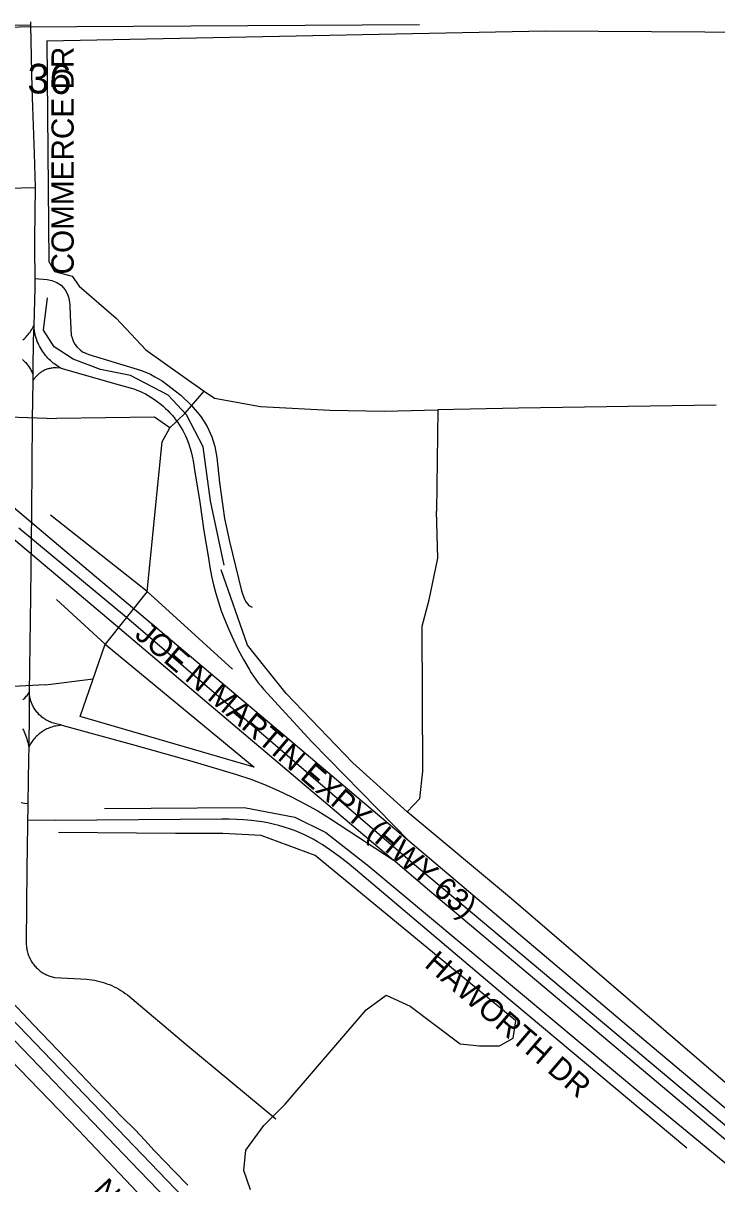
# Model space of a CAD drawing. Extents: x 1670563 to 1761545, y 515755 to 578944.
# Drawn here: x 1720123 to 1722466, y 535106 to 539024 of the extents above; entities that cross this region are included whole.
import ezdxf

# ---------------------------------------------------------------- set-up
doc = ezdxf.new("R2010")
doc.units = 0
for name, color, linetype in [('5_sectionlines', 7, 'Continuous'), ('62_text', 7, 'Continuous'), ('RR Tracks', 7, 'Continuous'), ('SHP_LINE', 7, 'Continuous'), ('STREETCL', 7, 'Continuous'), ('STRNAMES', 7, 'Continuous')]:
    doc.layers.add(name, color=color, linetype=linetype)

# ---------------------------------------------------------------- blocks, each defined once
blk = doc.blocks.new('RR TRACKS02')
at = {"layer": 'RR Tracks'}
for p, q in [((1720066.6, 535738.8), (1720158.1, 535642.9)), ((1720158.1, 535642.9), (1720268.9, 535527.6)), ((1720268.9, 535527.6), (1720363.3, 535429)), ((1720363.3, 535429), (1720404.7, 535386)), ((1720404.7, 535386), (1720455, 535333.2)), ((1720455, 535333.2), (1720500.9, 535287.8)), ((1720500.9, 535287.8), (1720534.1, 535252.7)), ((1720534.1, 535252.7), (1720566.1, 535218.7)), ((1720566.1, 535218.7), (1720605, 535177.4)), ((1720605, 535177.4), (1720631.5, 535150.1)), ((1720631.5, 535150.1), (1720678.7, 535101))]:
    blk.add_line(p, q, dxfattribs=at)

msp = doc.modelspace()

# ---------------------------------------------------------------- linework, layer by layer
at = {"layer": '5_sectionlines'}
msp.add_lwpolyline([(1717513.9, 538978.6), (1720109.2, 539011.6), (1721461.9, 539019.1)], dxfattribs=at)
at = {"layer": 'SHP_LINE'}
for points in [[(1720203, 538964), (1721887, 538998), (1722783, 538992), (1723831, 538992), (1723868, 538974), (1723856, 537753)], [(1720203, 538964), (1720210, 538219), (1720229, 538185), (1720289, 538170), (1720312, 538136), (1720437, 538028), (1720537, 537921), (1720662, 537832), (1720734, 537782)], [(1716945, 538927), (1717499, 538359), (1718014, 537823), (1718693, 537111), (1720080, 535667), (1721972, 533700)], [(1720675, 537702), (1720613, 537768), (1720486, 537834), (1720384, 537855), (1720292, 537890), (1720228, 537931), (1720192, 537987), (1720205, 538097)], [(1719435, 538027), (1720006, 537568), (1720055, 537550), (1720058, 537652), (1720074, 537695), (1720236, 537689)], [(1720670, 537707), (1720734, 537782)], [(1720734, 537782), (1720769, 537758), (1720925, 537730), (1721159, 537717), (1721343, 537714), (1721524, 537719)], [(1722464, 537734), (1721796, 537724), (1721524, 537719)], [(1720618, 537658), (1720567, 537694), (1720236, 537689)], [(1720618, 537658), (1720670, 537707)], [(1720802, 537194), (1720756, 537411), (1720731, 537594), (1720675, 537702)], [(1721524, 537719), (1721519, 537376)], [(1720542, 537105), (1720593, 537610), (1720618, 537658)], [(1720542, 537105), (1720215, 537363)], [(1721420, 536361), (1721463, 536407), (1721473, 536499), (1721471, 536988), (1721494, 537077), (1721524, 537218), (1721519, 537376)], [(1720472, 537018), (1720108, 537319)], [(1721420, 536361), (1721236, 536527), (1721011, 536761), (1720881, 536924), (1720792, 537179)], [(1720400, 536928), (1720236, 537078)], [(1720542, 537105), (1720400, 536928)], [(1720830, 536843), (1720542, 537105)], [(1722723, 535111), (1721430, 536195), (1720472, 537018)], [(1720316, 536683), (1720400, 536928)], [(1720400, 536928), (1720903, 536512)], [(1720198, 536790), (1720359, 536810)], [(1720198, 536790), (1720088, 536785)], [(1720903, 536512), (1720316, 536683)], [(1720398, 536373), (1720869, 536376), (1721041, 536343), (1721145, 536292), (1721291, 536178), (1722213, 535409), (1722571, 535114)], [(1722791, 535192), (1721772, 536068), (1721420, 536361)], [(1720891, 535086), (1720868, 535151), (1720875, 535219), (1720936, 535303), (1721008, 535375), (1721281, 535693), (1721349, 535743), (1721430, 535705), (1721599, 535578), (1721664, 535572), (1721732, 535572), (1721778, 535598), (1721787, 535656), (1721109, 536214), (1720927, 536282), (1720797, 536288), (1720638, 536288), (1720242, 536292)], [(1721755, 533769), (1721429, 534123), (1720982, 534585), (1720746, 534827), (1720310, 535287), (1719979, 535628)]]:
    msp.add_lwpolyline(points, dxfattribs=at)
at = {"layer": 'STREETCL'}
for points in [[(1720148.4, 539028), (1720148.2, 539016.9)], [(1720148.2, 539016.9), (1719670.9, 539012.9), (1719127.6, 539007.3)], [(1720148.2, 539016.9), (1720152.9, 538804.9), (1720160.8, 538584.1), (1720163.3, 538468.9)], [(1717072.9, 538715.7), (1717264.4, 538514.7), (1717510.3, 538264.3), (1717644.4, 538130.2), (1717873.6, 537900.7), (1718183.4, 537583.4), (1718347.1, 537415.1), (1718556.6, 537194.6), (1718908.4, 536828.7), (1719250.4, 536472.2), (1719637.9, 536070.3), (1720069.6, 535615.9), (1720515, 535151.1), (1721005.6, 534643.8), (1721526.6, 534096.2), (1721830.2, 533779.6)], [(1719874.9, 538462.2), (1720163.3, 538468.9)], [(1720163.3, 538468.9), (1720163, 538382.3), (1720160.9, 538295.8), (1720162.5, 538130.2), (1720158.6, 538002.8)], [(1718950.4, 538352.1), (1719123.4, 538207), (1719173, 538165), (1719214.3, 538129.6), (1719589.5, 537811.7), (1720242.3, 537262), (1721005.8, 536619.3), (1721524.5, 536180.2), (1722198.3, 535611.1), (1722953.7, 534976), (1723788.9, 534274.5), (1724544.5, 533631.9), (1724982.8, 533261.7), (1725686.8, 532669.5), (1726432.6, 532038.6), (1727302.6, 531305.4), (1727848.2, 530843.4), (1728084.3, 530646.1), (1728237.3, 530523.1), (1728394.2, 530405.1)], [(1718979.7, 538220.5), (1719085.6, 538130.6), (1719464.7, 537808.7), (1719917.2, 537427.8), (1720391.1, 537029.5), (1720831.3, 536657.3), (1721210.7, 536336.3), (1721372.6, 536199.1)], [(1720162.2, 538162), (1720204.5, 538158.4), (1720219.7, 538155.5), (1720236.3, 538148.1), (1720251.1, 538138.9), (1720264.4, 538124.1), (1720273.3, 538109), (1720277.7, 538095.3), (1720279.9, 538081.3), (1720281, 538072.4), (1720282.1, 538037), (1720285.1, 537971), (1720288.1, 537961.4), (1720292.2, 537950.3), (1720298.1, 537940.7), (1720305.5, 537930), (1720315.1, 537920.8), (1720323.9, 537914.5), (1720337.2, 537908.2), (1720345.4, 537905.3), (1720523.2, 537851.5), (1720552.8, 537838.9), (1720567.9, 537830.1), (1720593.1, 537816.4), (1720607.5, 537805.3), (1720655.4, 537768.2), (1720691.2, 537733.2), (1720723.7, 537695.9), (1720744.8, 537662.6), (1720760.7, 537627.6), (1720770, 537594.8), (1720777.4, 537557.9), (1720786.3, 537473), (1720803, 537351.2), (1720820.3, 537273.7), (1720860.2, 537107.9), (1720869.1, 537082.1), (1720875.8, 537068.9), (1720885.4, 537057.8), (1720896.9, 537051.9)], [(1720122.5, 537954.8), (1720126.3, 537958.2), (1720129.9, 537961.7), (1720133.5, 537965.3), (1720136.9, 537969), (1720140.2, 537972.9), (1720143.3, 537976.9), (1720146.3, 537981), (1720149.2, 537985.1), (1720151.9, 537989.4), (1720154.5, 537993.8), (1720156.9, 537998.3), (1720158.6, 538002.4)], [(1720158.6, 538002.8), (1720157.2, 537953.6), (1720155.8, 537853.7)], [(1720249.9, 537859.5), (1720244.6, 537862.6), (1720239.5, 537865.8), (1720234.4, 537869.3), (1720229.5, 537872.9), (1720224.7, 537876.6), (1720220, 537880.5), (1720215.4, 537884.6), (1720211, 537888.8), (1720206.8, 537893.2), (1720202.7, 537897.7), (1720198.7, 537902.4), (1720194.9, 537907.2), (1720191.3, 537912.1), (1720187.9, 537917.1), (1720184.6, 537922.3), (1720181.5, 537927.5), (1720178.6, 537932.9), (1720175.8, 537938.3), (1720173.3, 537943.9), (1720170.9, 537949.5), (1720168.8, 537955.2), (1720166.8, 537961), (1720165, 537966.8), (1720163.4, 537972.7), (1720162.1, 537978.7), (1720160.9, 537984.7), (1720159.9, 537990.7), (1720159.2, 537996.7), (1720158.6, 538002.8)], [(1720120.7, 537888.3), (1720123.6, 537885.8), (1720126.4, 537883.2), (1720129.2, 537880.5), (1720131.9, 537877.8), (1720134.5, 537874.9), (1720136.9, 537872), (1720139.3, 537869), (1720141.6, 537865.9), (1720143.7, 537862.7), (1720145.8, 537859.4), (1720147.7, 537856.1), (1720149.5, 537852.7), (1720151.2, 537849.3), (1720152.8, 537845.8), (1720154.3, 537842.2), (1720155.6, 537838.6)], [(1720249.9, 537859.5), (1720236, 537860.2), (1720233, 537860.3), (1720230, 537860.3), (1720226.9, 537860.1), (1720223.9, 537859.9), (1720220.9, 537859.6), (1720217.9, 537859.1), (1720214.9, 537858.6), (1720211.9, 537858), (1720209, 537857.2), (1720206.1, 537856.4), (1720203.2, 537855.4), (1720200.3, 537854.4), (1720197.5, 537853.3), (1720194.7, 537852), (1720192, 537850.7), (1720189.3, 537849.3), (1720186.7, 537847.8), (1720184.1, 537846.1), (1720181.6, 537844.5), (1720179.2, 537842.7), (1720176.8, 537840.8), (1720174.4, 537838.9), (1720172.2, 537836.8), (1720170, 537834.7), (1720167.9, 537832.6), (1720165.8, 537830.3), (1720163.9, 537828), (1720162, 537825.6), (1720160.2, 537823.2), (1720158.5, 537820.7), (1720156.9, 537818.1), (1720155.3, 537815.5)], [(1720155.8, 537853.7), (1720155.3, 537815.5)], [(1720249.9, 537859.5), (1720451.6, 537802.3), (1720497.3, 537788.9), (1720507.1, 537785.2), (1720516.8, 537781.1), (1720526.4, 537776.7), (1720535.8, 537772), (1720545, 537766.9), (1720554.1, 537761.6), (1720562.9, 537755.9), (1720571.6, 537750), (1720580.1, 537743.7), (1720588.3, 537737.2), (1720596.3, 537730.4), (1720604.1, 537723.3), (1720611.7, 537716), (1720619, 537708.4), (1720626, 537700.6), (1720632.7, 537692.5), (1720639.2, 537684.2), (1720645.4, 537675.7), (1720651.3, 537667), (1720656.9, 537658.1), (1720662.2, 537649), (1720667.2, 537639.8), (1720671.8, 537630.3), (1720676.2, 537620.7), (1720681.4, 537606.2), (1720686.1, 537591.6), (1720690.3, 537576.8), (1720694, 537561.8), (1720697.3, 537546.8), (1720700, 537531.6), (1720702.3, 537516.4), (1720719.8, 537406.8), (1720733.6, 537310.1), (1720749.2, 537217.6), (1720753.8, 537187.5), (1720759.4, 537157.6), (1720766.1, 537127.9), (1720773.7, 537098.4), (1720782.4, 537069.2), (1720792.1, 537040.3), (1720802.8, 537011.8), (1720817.3, 536977), (1720833, 536942.7), (1720849.7, 536908.9), (1720867.4, 536875.7), (1720886.2, 536843), (1720893.4, 536831.3), (1720900.9, 536819.7), (1720908.7, 536808.4), (1720917, 536797.4), (1720925.5, 536786.6), (1720934.4, 536776.1), (1721097.6, 536598), (1721429.5, 536260.6)], [(1720155.3, 537815.5), (1720153.6, 537686.9), (1720151, 537372.1), (1720147.4, 537088.2), (1720143.8, 536763.9)], [(1720122.3, 536740.6), (1720125.3, 536743.2), (1720128.3, 536745.8), (1720131.1, 536748.6), (1720133.8, 536751.5), (1720136.5, 536754.5), (1720139, 536757.5), (1720141.5, 536760.7), (1720143.8, 536763.9)], [(1720143.8, 536763.9), (1720143, 536696.7), (1720141.7, 536578.7)], [(1720253.9, 536653.7), (1720225.1, 536661.1), (1720221.3, 536662.3), (1720217.5, 536663.6), (1720213.8, 536665.1), (1720210.2, 536666.8), (1720206.6, 536668.5), (1720203.1, 536670.4), (1720199.6, 536672.4), (1720196.3, 536674.5), (1720193, 536676.7), (1720189.7, 536679), (1720186.6, 536681.5), (1720183.5, 536684), (1720180.6, 536686.7), (1720177.7, 536689.4), (1720174.9, 536692.3), (1720172.2, 536695.2), (1720169.6, 536698.3), (1720167.2, 536701.4), (1720164.8, 536704.6), (1720162.6, 536707.9), (1720160.4, 536711.2), (1720158.4, 536714.7), (1720156.5, 536718.2), (1720154.8, 536721.7), (1720153.1, 536725.4), (1720151.6, 536729), (1720150.2, 536732.8), (1720148.9, 536736.6), (1720147.8, 536740.4), (1720146.8, 536744.2), (1720145.9, 536748.1), (1720145.2, 536752), (1720144.6, 536756), (1720144.1, 536759.9), (1720143.8, 536763.9)], [(1720121.4, 536642.1), (1720124.2, 536636.7), (1720126.9, 536631.2), (1720129.3, 536625.6), (1720131.5, 536620), (1720133.6, 536614.3), (1720135.4, 536608.5), (1720137.1, 536602.6), (1720138.6, 536596.7), (1720139.8, 536590.7), (1720140.8, 536584.7), (1720141.7, 536578.7)], [(1720253.9, 536653.7), (1720233.2, 536651.2), (1720228.8, 536650.2), (1720224.4, 536649.1), (1720220.1, 536647.8), (1720215.9, 536646.4), (1720211.7, 536644.8), (1720207.6, 536643.1), (1720203.5, 536641.2), (1720199.5, 536639.2), (1720195.5, 536637.1), (1720191.7, 536634.8), (1720187.9, 536632.4), (1720184.2, 536629.9), (1720180.6, 536627.2), (1720177.1, 536624.4), (1720173.6, 536621.5), (1720170.3, 536618.5), (1720167.1, 536615.4), (1720164, 536612.1), (1720161, 536608.8), (1720158.2, 536605.3), (1720155.4, 536601.8), (1720152.8, 536598.1), (1720150.3, 536594.4), (1720148, 536590.6), (1720145.7, 536586.7), (1720143.6, 536582.7), (1720141.7, 536578.7)], [(1720253.9, 536653.7), (1720492.3, 536589), (1720700.6, 536530.4), (1720844.1, 536488), (1720891.5, 536471.5), (1720938.3, 536453.3), (1720984.4, 536433.5), (1721029.8, 536412.1), (1721074.4, 536389.1), (1721118.2, 536364.5), (1721161.1, 536338.4), (1721372.6, 536199.1)], [(1720141.7, 536578.7), (1720141.3, 536542.7), (1720139.1, 536389.7)], [(1720116.2, 536393), (1720127.6, 536391.2), (1720139.1, 536389.7)], [(1720139.1, 536389.7), (1720136, 536169.4), (1720133.4, 535920.5)], [(1722364.5, 535226.1), (1721728.6, 535758.3), (1721245.4, 536167), (1721218.2, 536189.3), (1721190.2, 536210.7), (1721161.7, 536231.3), (1721132.4, 536250.9), (1721117.6, 536260.1), (1721102.5, 536268.8), (1721087, 536277), (1721071.3, 536284.7), (1721055.3, 536291.7), (1721039.1, 536298.2), (1721022.6, 536304.2), (1721004.6, 536310), (1720986.3, 536315.2), (1720967.9, 536319.9), (1720949.4, 536323.9), (1720930.8, 536327.3), (1720912, 536330.2), (1720893.2, 536332.4), (1720868.5, 536334.5), (1720843.8, 536335.9), (1720819.1, 536336.5), (1720794.3, 536336.3), (1720231.4, 536332.5), (1720138.3, 536333.8)], [(1728653.2, 530115.7), (1728352.7, 530332.4), (1728275.7, 530388.1), (1728200.3, 530445.9), (1728126.6, 530505.9), (1727694.6, 530868), (1727158, 531319.4), (1726440.9, 531926.6), (1726228.5, 532103.9), (1725809, 532459.7), (1725505.4, 532713.2), (1725193.8, 532977.5), (1725010.1, 533132.4), (1724856.7, 533260.6), (1724520.2, 533546.7), (1723891, 534077.5), (1723306.1, 534568.7), (1722651.6, 535122.4), (1722033.9, 535643), (1721503.5, 536088.2), (1721372.6, 536199.1)], [(1720133.4, 535920.5), (1720133.4, 535916.3), (1720133.6, 535912.2), (1720133.9, 535908.1), (1720134.4, 535904), (1720135, 535899.9), (1720135.7, 535895.9), (1720136.6, 535891.9), (1720137.6, 535887.9), (1720138.8, 535883.9), (1720140.1, 535880), (1720141.5, 535876.1), (1720143.1, 535872.3), (1720144.8, 535868.6), (1720146.6, 535864.9), (1720148.5, 535861.2), (1720150.6, 535857.7), (1720152.8, 535854.2), (1720155.1, 535850.8), (1720157.6, 535847.4), (1720160.1, 535844.2), (1720162.8, 535841), (1720165.5, 535838), (1720168.4, 535835), (1720171.4, 535832.2), (1720174.4, 535829.4), (1720177.6, 535826.8), (1720180.8, 535824.2), (1720184.2, 535821.8), (1720187.6, 535819.5), (1720191.1, 535817.3), (1720194.7, 535815.2), (1720198.3, 535813.3), (1720202, 535811.5), (1720205.8, 535809.8), (1720209.6, 535808.3), (1720213.4, 535806.8), (1720217.4, 535805.6), (1720221.3, 535804.4), (1720225.3, 535803.4), (1720229.4, 535802.5), (1720337.6, 535796.4), (1720346.4, 535795.6), (1720355.1, 535794.4), (1720363.7, 535793), (1720372.3, 535791.3), (1720380.9, 535789.2), (1720389.4, 535786.9), (1720397.7, 535784.3), (1720406, 535781.5), (1720414.2, 535778.3), (1720422.3, 535774.9), (1720430.3, 535771.2), (1720438.1, 535767.3), (1720445.8, 535763), (1720453.3, 535758.5), (1720460.7, 535753.8), (1720468, 535748.8), (1720475, 535743.6), (1720672.6, 535576.9), (1720975.9, 535325.7)]]:
    msp.add_lwpolyline(points, dxfattribs=at)

# ---------------------------------------------------------------- block references
msp.add_blockref('RR TRACKS02', (0, 0), dxfattribs=at)

# ---------------------------------------------------------------- texts
at = {"layer": '62_text'}
msp.add_text('36', height=100, rotation=358.9328, dxfattribs=at).set_placement((1720136.9, 538787.2))
at = {"layer": 'STRNAMES'}
for s, rotation, p in [('COMMERCE DR', 90, (1720293.7, 538175.5)), ('JOE N MARTIN EXPY (HWY 63)', 319.4732, (1720495.9, 536953.7)), ('HAWORTH DR', 319.3865, (1721475.1, 535841.1)), ('NETTLETON AVE (HWY 463)', 312.7601, (1720353.3, 535080.5))]:
    msp.add_text(s, height=75, rotation=rotation, dxfattribs=at).set_placement(p)

doc.saveas('drawing.dxf')
